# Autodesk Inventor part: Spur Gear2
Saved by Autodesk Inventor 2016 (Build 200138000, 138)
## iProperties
Created: 2016-10
Part Number: Spur Gear2
Material: Steel
Document SubType Name: Modeling
Designer: Ingenieria
Categories: <?xml version="1.0" encoding="UTF-16"?> <MemberInstance><Categories><FamilyTemplate><FamilyTemplateParameter ValueType="xs:double" Id="1" ObjectReferenceKey="da
Density: 1 g/cm^3
Appearance: Steel
CustomPartVersion: 1
Author: Ingenieria
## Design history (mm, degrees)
sketch "Sketch1"
  geometry: C1 r 266.187 at (0, 0)
  constraints: 1 centre point
  dimensions: "d0" = 532.37337 diameter of C1 (= da_da)
extrude "Extrusion1" new body sketch "Sketch1" distance "d1" = 60 (= da_b); taper "d2" = 0 deg
workplane "Work Plane2"
sketch "Sketch2"
  geometry: C1 r 266.187 at (0, 0) reference; C2 r 261.193 at (0, 0)
  constraints: 1 centre point, 1 coincident
  dimensions: "d3" = 522.38588 diameter of C2 (= da_dw)
feature "Pitch Diameter" sketch "Sketch2" dims "d4" = 10, "d5" = 0
workplane "Work Plane8"
workplane "Work Plane9"
feature "Spur Gear" dims "d4" = 10, "d5" = 0, "da_b" = 60, "da_d" = 520, "da_aw" = 341.56, "da_da" = 532.37337, "da_df" = 509.92655, "da_dw" = 522.38588, angle "da_beta" = 0 deg, "da_lefttooth" = 0, "da_righttooth" = 0
body "Solid1"
body "Srf1"
other parameters: "d16" = 341.56 (= da_aw), "d17" = 0, "d34" = 0.30208 (computed from da_z), "d39" = 0, "d41" = 0, "d43" = 341.56 (= da_aw), "d46" = 341.56 (= da_aw), "d47" = 0, "d48" = 0
